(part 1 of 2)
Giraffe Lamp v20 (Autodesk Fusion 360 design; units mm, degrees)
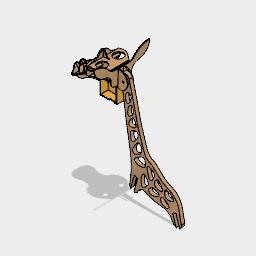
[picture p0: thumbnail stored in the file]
parameter "Thickness" = 3 comment "Material thickness"
parameter "Face1_to_2" = 15 comment "Distance between Face_1 and Face_2"
parameter "M6" = 6 comment "Screw M6"
parameter "Lamp_Socket_Diameter" = 32 comment "Lamp socket"
parameter "Lamp_Wires" = 12 comment "Hole to pass lamp wires"
parameter "Face_2_X" = 165.2206
parameter "pcb_holder_thickness" = 3
parameter "pcb_X" = 52
parameter "pcb_Y" = 49
canvas "Canvas1"
sketch "Body" plane through (0, 0, 0) normal (0, 1, 0) x axis (1, 0, 0)
  curve K1 (162.6914, -108.0349) -> (-15.6199, 232.4021)
  curve K2 (-43.7551, 223.7539) -> (-13.0647, -75.0438)
  curve K3 (-18.2431, 191.7214) -> (-18.2431, 191.7214)
  curve K4 (-7.5042, 158.394) -> (-7.5042, 158.394)
  curve K5 (-2.6903, 124.8814) -> (-2.6903, 124.8814)
  curve K6 (3.0035, 89.8922) -> (3.0035, 89.8922)
  curve K7 (17.7017, 60.8678) -> (17.7017, 60.8678)
  curve K8 (33.8884, 25.1455) -> (33.8884, 25.1455)
  curve K9 (51.6491, 8.676) -> (51.6491, 8.676)
  curve K10 (73.9532, -21.6154) -> (73.9532, -21.6154)
  curve K11 (105.4503, -39.5491) -> (105.4503, -39.5491)
  curve K12 (93.9968, -61.5519) -> (93.9968, -61.5519)
  curve K13 (60.842, -48.4407) -> (60.842, -48.4407)
  curve K14 (34.1675, -21.6154) -> (34.1675, -21.6154)
  curve K15 (15.9684, -79.8842) -> (135.1539, -116.9624)
  curve K16 (11.0078, -92.579) -> (20.9289, -67.1894)
  line L1 (14.1391, -44.6593) -> (2.5936, -41.388)
  line L2 (-10.0602, -86.0485) -> (2.5936, -41.388)
  line L3 (0.817, -91.6784) -> (14.1391, -44.6593)
  line L4 (144.6007, -83.0043) -> (133.1606, -86.627)
  line L5 (145.1038, -124.3424) -> (133.1606, -86.627)
  line L6 (156.8681, -121.7435) -> (144.6007, -83.0043)
  arc A1 centre (1.5341, -76.9705) radius 14.7254 clockwise from (-10.0602, -86.0485) to (-13.0647, -75.0435)
  arc A2 centre (1.5341, -76.9705) radius 14.7254 clockwise from (15.9684, -79.8842) to (0.817, -91.6784)
  arc A3 centre (148.0875, -109.9224) radius 14.7254 clockwise from (145.1038, -124.3424) to (135.1539, -116.9624)
  arc A4 centre (148.0875, -109.9224) radius 14.7254 clockwise from (162.6914, -108.0349) to (156.8681, -121.7435)
  arc A5 centre (-29.8322, 228.5489) radius 14.7254 clockwise from (-43.7487, 223.7354) to (-15.4135, 231.5383)
  circle C1 centre (-30, 220) radius 3
  point P157 (2.5936, -41.388)
  point P158 (14.1391, -44.6593)
  point P161 (133.1606, -86.627)
  point P162 (144.6007, -83.0043)
  dimension "d1" distance P157 P158 = 12
  dimension "d2" distance P161 P162 = 12
  dimension "d773" diameter C1 = 6 (= "M6")
extrude "Extrude1" new body sketch "Body" profile of A5 A4 A2 K1 K15 K2 K3 K4 K5 K6 K7 K8 K9 K10 K11 K12 K13 K14 L1 L2 L3 L4 L5 L6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 along normal blind 12 OffsetX 0 OffsetY 0 OffsetZ 0 AngleZ 0 OffsetX 0 OffsetY 0 OffsetZ 0 AngleZ 0 OffsetX 0 OffsetY 0 OffsetZ 0 AngleZ 0
sketch "Front legs" plane through (24.8016, 0, 7.0271) normal (-0.9621, 0, -0.2726) x axis (-0.2726, 0, 0.9621)
  line L1 (87.9835, 0) -> (39.1135, 0)
  line L2 (87.9835, 12) -> (87.9835, 0)
  line L3 (39.1135, 12) -> (87.9835, 12)
  line L4 (39.1135, 0) -> (39.1135, 12)
  line L5 (256.8278, 66) -> (256.8278, -54)
  line L6 (39.1135, -5.4191) -> (39.1135, 17.4191)
  line L7 (257.1251, -36.0025) -> (256.8278, -54)
  line L8 (87.9835, 0) -> (257.1251, -36.0025)
  line L9 (257.1251, 48.0025) -> (256.8278, 66)
  line L10 (87.9835, 12) -> (257.1251, 48.0025)
  line L11 (87.9835, 12) -> (87.9835, 0)
  line L12 (14.8278, 0) -> (87.9835, 0)
  line L13 (87.9835, 12) -> (14.8278, 12)
  line L14 (39.1135, 12) -> (39.1135, 0)
  line L15 (256.8278, -54) -> (14.8278, 0)
  line L16 (256.8278, 66) -> (14.8278, 12)
  line L17 (39.1135, 6) -> (256.8278, 6)
  line L18 (14.8278, 12) -> (14.8278, 0)
  line L19 (14.8278, 6) -> (39.1135, 6)
  point P6 (256.8278, -54)
  point P8 (257.1251, -36.0025)
  point P7 (256.8278, 66)
  point P10 (257.1251, 48.0025)
  point P9 (87.9835, 0)
  point P11 (87.9835, 12)
  point P17 (256.8278, 6)
  point P21 (14.8278, 6)
  dimension "d22" distance P6 P8 = 18
  dimension "d23" distance P7 P10 = 18
  dimension "d25" distance P9 P11 = 12
  dimension "d26" distance P6 P7 = 120
  dimension "d27" distance P17 P21 = 242
extrude "Extrude1" sketch "Front legs" profile of L1 L2 L3 L4 L5 L6 L8 L10 L11 L12 L13 L14 L15 L16 blind 12
sketch "Rear legs" plane through (107.5328, 0, -34.0521) normal (-0.9533, 0, 0.3019) x axis (0.3019, 0, 0.9533)
  line L1 (163.4204, 0) -> (122.7853, 0)
  line L2 (163.4204, 12) -> (163.4204, 0)
  line L3 (122.7853, 12) -> (163.4204, 12)
  line L4 (122.7853, 0) -> (122.7853, 12)
  line L5 (299.7658, 66) -> (101.7658, 66)
  line L6 (299.7658, -54) -> (299.7658, 66)
  line L7 (101.7658, -54) -> (299.7658, -54)
  line L8 (101.7658, 66) -> (101.7658, -54)
  line L9 (299.7658, 6) -> (101.7658, 6)
  line L10 (122.7853, 0) -> (122.7853, 6)
  line L11 (163.4204, 0) -> (101.7658, 0)
  line L12 (163.4204, 0) -> (163.4204, 6)
  line L13 (122.7853, 6) -> (122.7853, 0)
  line L14 (299.7658, -54) -> (101.7658, 0)
  line L15 (299.7658, -37.1851) -> (163.4204, 0)
  line L16 (299.7658, 66) -> (101.7658, 12)
  line L17 (299.7658, 49.1851) -> (163.4204, 12)
  line L18 (163.4204, 12) -> (101.7658, 12)
  line L19 (122.7853, 6) -> (122.7853, 12)
  line L20 (163.4204, 12) -> (163.4204, 6)
  point P6 (101.7658, 66)
  point P9 (101.7658, -54)
  point P8 (299.7658, -54)
  point P12 (122.7853, 6)
  point P13 (122.7853, 0)
  dimension "d30" distance P6 P9 = 120
  dimension "d31" distance P8 P9 = 198
  dimension "d32" distance P12 P13 = 6
extrude "Extrude1" new body sketch "Rear legs" profile of L1 L2 L3 L4 L6 L10 L11 L12 L13 L14 L15 L16 L17 L18 L19 L20 along normal blind 12
work_plane "WorkPlane1" AlongDistance 250
split "Split1"
remove_body "RemoveBody1"
remove_body "RemoveBody2"
remove_body "RemoveBody1"
remove_body "RemoveBody2"
as_built_joint "As-built1"
as_built_joint "As-built2"
sketch "Face_1" plane through (-225, 0, 0) normal (0, 1, 0) x axis (1, 0, 0)
  line L1 (-103.7104, 33.9723) -> (-78.2357, 50.7747)
  line L2 (-76.5839, 48.2704) -> (-102.5614, 31.1364)
  line L3 (-138.7738, 52.2663) -> (-135.7747, 52.34)
  line L4 (-138.5282, 42.2693) -> (-138.7738, 52.2663)
  line L5 (-179.6538, 49.3613) -> (-176.6874, 48.9131)
  line L6 (-68.885, 40.3968) -> (-28.0159, 61.0056)
  line L7 (-110.8466, 47.166) -> (-103.7104, 33.9723)
  line L8 (-179.6538, 49.3613) -> (-176.6874, 48.9131)
  line L9 (-181.365, 38.0363) -> (-179.6538, 49.3613)
  line L10 (-166.5197, 41.5814) -> (-156.5227, 41.8271)
  line L11 (-138.5282, 42.2693) -> (-138.7738, 52.2663)
  line L12 (-76.5839, 48.2704) -> (-102.5614, 31.1364)
  line L13 (-156.7684, 51.8241) -> (-153.7693, 51.8978)
  line L14 (-156.7684, 51.8241) -> (-153.7693, 51.8978)
  line L15 (-153.5236, 41.9008) -> (-138.5282, 42.2693)
  line L16 (-121.518, 60.6927) -> (-199.0216, 58.7881)
  line L17 (-166.5197, 41.5814) -> (-156.5227, 41.8271)
  line L18 (-121.5917, 63.6918) -> (-121.518, 60.6927)
  line L19 (-135.7747, 52.34) -> (-135.5291, 42.3447)
  line L20 (-181.365, 38.0363) -> (-179.6538, 49.3613)
  line L21 (-121.5917, 63.6918) -> (-121.518, 60.6927)
  line L22 (-110.8466, 47.166) -> (-103.7104, 33.9723)
  line L23 (-68.885, 40.3968) -> (-28.0159, 61.0056)
  line L24 (-176.6874, 48.9131) -> (-178.479, 37.0562)
  line L25 (-176.6874, 48.9131) -> (-178.479, 37.0562)
  line L26 (-78.2357, 50.7747) -> (-76.5839, 48.2704)
  line L27 (-78.2357, 50.7747) -> (-76.5839, 48.2704)
  line L28 (-106.2966, 32.4478) -> (-113.4853, 45.7388)
  line L29 (-153.7693, 51.8978) -> (-153.5236, 41.9008)
  line L30 (-138.7738, 52.2663) -> (-135.7747, 52.34)
  line L31 (-135.7747, 52.34) -> (-135.5291, 42.3447)
  line L32 (-106.2966, 32.4478) -> (-113.4853, 45.7388)
  line L33 (-113.4853, 45.7388) -> (-110.8466, 47.166)
  line L34 (-36.7376, 81.1397) -> (-25.2825, 62.2843)
  line L35 (-135.5291, 42.3447) -> (-127.5161, 42.5416)
  line L36 (-156.5227, 41.8271) -> (-156.7684, 51.8241)
  line L37 (-113.4853, 45.7388) -> (-110.8466, 47.166)
  line L38 (-121.518, 60.6927) -> (-199.0216, 58.7881)
  line L39 (-153.7693, 51.8978) -> (-153.5236, 41.9008)
  line L40 (-39.3015, 79.5821) -> (-36.7376, 81.1397)
  line L41 (-28.0159, 61.0056) -> (-39.3015, 79.5821)
  line L42 (-103.7104, 33.9723) -> (-78.2357, 50.7747)
  line L43 (-135.5291, 42.3447) -> (-127.5161, 42.5416)
  line L44 (-156.5227, 41.8271) -> (-156.7684, 51.8241)
  line L45 (-28.0159, 61.0056) -> (-39.3015, 79.5821)
  line L46 (-36.7376, 81.1397) -> (-25.2825, 62.2843)
  line L47 (-153.5236, 41.9008) -> (-138.5282, 42.2693)
  line L48 (-198.9101, 61.7918) -> (-121.5917, 63.6918)
  line L49 (-39.3015, 79.5821) -> (-36.7376, 81.1397)
  line L50 (-198.9101, 61.7918) -> (-121.5917, 63.6918)
  line L51 (-57.521, 46.1272) -> (-28.0159, 61.0056)
  line L52 (-87.645, 105.8658) -> (-57.521, 46.1272)
  line L53 (-31.0003, 65.918) -> (-198.9101, 61.7918)
  arc A1 centre (-63.0365, 19.3769) radius 21.8183 clockwise from (-76.4762, 36.5645) to (-68.885, 40.3968)
  arc A2 centre (-63.0365, 19.3769) radius 21.8183 clockwise from (-76.4762, 36.5645) to (-68.885, 40.3968)
  arc A3 centre (-95.0013, 60.1969) radius 30.0278 between (-102.5614, 31.1364) and (-76.4762, 36.5645)
  arc A4 centre (-40.0004, 104.4994) radius 15.4992 between (-40, 119.9986) and (-53.1678, 112.6753)
  arc A5 centre (-176.093, 48.8166) radius 12.0003 between (-186.4762, 42.8002) and (-181.365, 38.0363)
  arc A6 centre (-176.0931, 48.8167) radius 12 between (-178.479, 37.0562) and (-166.5197, 41.5814)
  arc A7 centre (-127.0728, 24.5455) radius 18.0016 clockwise from (-127.5161, 42.5416) to (-115.0285, 37.9243)
  circle C1 centre (-26.8048, 98.0857) radius 3
  arc A8 centre (-94.9606, 60.2216) radius 29.9982 between (-115.0285, 37.9243) and (-106.2966, 32.4478)
  arc A9 centre (-178.7415, 61.7856) radius 20.5005 between (-199.0216, 58.7881) and (-186.4762, 42.8002)
  arc A10 centre (-67.6106, 121.6427) radius 17.0002 clockwise from (-53.1678, 112.6753) to (-72.6595, 105.4096)
  arc A11 centre (-80.9733, 78.6726) radius 27.9997 between (-72.6595, 105.4096) and (-99.1949, 99.932)
  arc A12 centre (-95.0013, 60.1969) radius 30.0278 between (-102.5614, 31.1364) and (-76.4762, 36.5645)
  arc A13 centre (-40.0043, 90.0088) radius 29.9898 between (-23.2866, 65.1109) and (-40, 119.9986)
  arc A14 centre (-127.0728, 24.5455) radius 18.0016 clockwise from (-127.5161, 42.5416) to (-115.0285, 37.9243)
  arc A15 centre (-157.7624, 168.2688) radius 90.0004 clockwise from (-99.1949, 99.932) to (-171.2531, 79.2852)
  arc A16 centre (-176.0931, 48.8167) radius 12 between (-178.479, 37.0562) and (-166.5197, 41.5814)
  arc A17 centre (-176.093, 48.8166) radius 12.0003 between (-186.4762, 42.8002) and (-181.365, 38.0363)
  arc A18 centre (-12.9246, 55.6761) radius 14.0138 clockwise from (-25.2825, 62.2843) to (-23.2866, 65.1109)
  arc A19 centre (-178.7415, 61.7856) radius 20.5005 between (-199.0216, 58.7881) and (-186.4762, 42.8002)
  arc A20 centre (-94.9606, 60.2216) radius 29.9982 between (-115.0285, 37.9243) and (-106.2966, 32.4478)
  arc A21 centre (-40.0004, 104.4994) radius 15.4992 between (-40, 119.9986) and (-53.1678, 112.6753)
  arc A22 centre (-174.9843, 54.5747) radius 24.9906 between (-171.2531, 79.2852) and (-198.9101, 61.7918)
  arc A23 centre (-12.9246, 55.6761) radius 14.0138 clockwise from (-25.2825, 62.2843) to (-23.2866, 65.1109)
  arc A24 centre (-67.6106, 121.6427) radius 17.0002 clockwise from (-53.1678, 112.6753) to (-72.6595, 105.4096)
  arc A25 centre (-80.9733, 78.6726) radius 27.9997 between (-72.6595, 105.4096) and (-99.1949, 99.932)
  arc A26 centre (-40.0043, 90.0088) radius 29.9898 between (-23.2866, 65.1109) and (-40, 119.9986)
  circle C2 centre (-26.8048, 98.0857) radius 3
  arc A27 centre (-157.7624, 168.2688) radius 90.0004 clockwise from (-99.1949, 99.932) to (-171.2531, 79.2852)
  arc A28 centre (-174.9847, 54.5754) radius 24.9899 between (-171.2531, 79.2852) and (-198.9101, 61.7918)
  circle C3 centre (-72.583, 75.9965) radius 6
  point P19 (-28.0159, 61.0056)
  point P71 (-57.521, 46.1272)
  point P7 (-103.7104, 33.9723)
  point P20 (-110.8466, 47.166)
  dimension "d42" distance L38 L48 = 3 (= "Thickness")
  dimension "d43" distance L9 L25 = 3 (= "Thickness")
  dimension "d44" distance L39 L44 = 3 (= "Thickness")
  dimension "d45" distance L4 L19 = 3 (= "Thickness")
  dimension "d46" distance L22 L32 = 3 (= "Thickness")
  dimension "d47" distance L1 L2 = 3 (= "Thickness")
  dimension "d48" distance L34 L45 = 3 (= "Thickness")
  dimension "d422" diameter C2 = 6 (= "M6")
  dimension "d720" distance P19 P71 = 33.0441 (= "Face_2_X / 5")
  dimension "d741" diameter C3 = 12 (= "Lamp_Wires")
  dimension "d835" distance P7 P20 = 15 (= "Face1_to_2")
sketch "3e_corne_2" plane through (-200, 0, 0) normal (0, 1, 0) x axis (1, 0, 0)
  line L1 (40.5, 96.1735) -> (10, 96.1735)
  line L2 (40.5, 99.1735) -> (40.5, 96.1735)
  line L3 (10, 101.0735) -> (10, 99.1735)
  line L4 (55.1493, 76.5991) -> (62, 96.1735)
  line L5 (62, 120) -> (10, 101.0735)
  line L6 (10, 99.1735) -> (40.5, 99.1735)
  line L7 (10, 99.1735) -> (40.5, 99.1735)
  line L8 (10, 96.1735) -> (10, 87.0735)
  line L9 (40.5, 96.1735) -> (10, 96.1735)
  line L10 (62, 96.1735) -> (62, 120)
  line L11 (10, 96.1735) -> (10, 87.0735)
  line L12 (10, 101.0735) -> (10, 99.1735)
  line L13 (55.1493, 76.5991) -> (62, 96.1735)
  line L14 (62, 96.1735) -> (62, 120)
  line L15 (62, 120) -> (10, 101.0735)
  line L16 (40.5, 99.1735) -> (40.5, 96.1735)
  arc A1 centre (43.133, 80.8046) radius 12.731 between (31.6545, 75.2979) and (55.1493, 76.5991)
  arc A2 centre (6.685, 55.1792) radius 32.0662 clockwise from (10, 87.0735) to (31.6545, 75.2979)
  arc A3 centre (43.133, 80.8046) radius 12.731 between (31.6545, 75.2979) and (55.1493, 76.5991)
  arc A4 centre (6.685, 55.1792) radius 32.0662 clockwise from (10, 87.0735) to (31.6545, 75.2979)
  dimension "d49" distance L1 L7 = 3 (= "Thickness")
sketch "Face_2" plane through (-375, 0, 175) normal (0, 1, 0) x axis (1, 0, 0)
  line L1 (-19, 32.297) -> (-19, 119.4441)
  line L2 (-1, 119.4441) -> (2, 119.4441)
  line L3 (2, 119.4441) -> (2, 32.297)
  line L4 (-16, 32.297) -> (-1, 32.297)
  line L5 (-16, 119.4441) -> (-16, 32.297)
  line L6 (-19, 119.4441) -> (-16, 119.4441)
  line L7 (-39.3235, 32.297) -> (-19, 32.297)
  line L8 (-54.2349, 53.4678) -> (-39.3235, 32.297)
  line L9 (22.3235, 32.297) -> (38.5, 52.5177)
  line L10 (-1, 32.297) -> (-1, 119.4441)
  line L11 (4, 197.5177) -> (-19, 197.5177)
  line L12 (2, 32.297) -> (22.3235, 32.297)
  arc A1 centre (-7.5, 171.6263) radius 32.1011 between (22.0518, 159.0895) and (24.0559, 177.5177)
  arc A2 centre (-7.5, 171.6263) radius 32.1011 between (-39.0559, 177.5177) and (-37.0518, 159.0895)
  arc A3 centre (-0.5195, 172.9296) radius 25 between (24.0559, 177.5177) and (4, 197.5177)
  arc A4 centre (-83.0811, 139.5624) radius 50 clockwise from (-37.0518, 159.0895) to (-49.5, 102.5177)
  arc A5 centre (68.0811, 139.5624) radius 50 clockwise from (34.5, 102.5177) to (22.0518, 159.0895)
  arc A6 centre (-14.4805, 172.9296) radius 25 between (-19, 197.5177) and (-39.0559, 177.5177)
  arc A7 centre (-24.9091, 75.3904) radius 36.6142 between (-49.5, 102.5177) and (-54.2349, 53.4678)
  arc A8 centre (9.9091, 75.3904) radius 36.6142 between (38.5, 52.5177) and (34.5, 102.5177)
  point P21 (-1, 32.297)
  point P22 (-16, 32.297)
  dimension "d50" distance L1 L5 = 3 (= "Thickness")
  dimension "d51" distance L3 L10 = 3 (= "Thickness")
  dimension "d306" distance P21 P22 = 15 (= "Face1_to_2")
  dimension "d716" distance L4 L11 = 165.2206 (= "Face_2_X")
sketch "Front" plane through (-167.3464, 0, 104.4808) normal (0, 1, 0) x axis (1, 0, 0)
  line L1 (-154.5591, 86) -> (-133.7744, 86)
  line L2 (-103.7, 89) -> (-106.7, 89)
  line L3 (-103.7, 67.9897) -> (-103.7, 89)
  line L4 (-87.0003, 67.9897) -> (-103.7, 67.9897)
  line L5 (-112.7, 120) -> (-97.7, 120)
  line L6 (-133.7744, 86) -> (-133.7744, 89)
  line L7 (-112.7, 98.5) -> (-112.7, 120)
  line L8 (-55.1377, 89) -> (-76.6256, 89)
  line L9 (-106.7, 89) -> (-106.7, 67.9972)
  line L10 (-116.7, 98.5) -> (-112.7, 98.5)
  line L11 (-97.7, 98.5) -> (-93.7, 98.5)
  line L12 (-76.6256, 89) -> (-76.6256, 86)
  line L13 (-76.6256, 86) -> (-55.4786, 86)
  line L14 (-97.7, 120) -> (-97.7, 98.5)
  line L15 (-152.7788, 98.5) -> (-116.7, 98.5)
  line L16 (-106.7, 67.9972) -> (-123, 67.9972)
  line L17 (-133.7744, 89) -> (-154.8709, 89)
  line L18 (-93.7, 98.5) -> (-57.2212, 98.5)
  line L19 (-154.8709, 89) -> (-154.8709, 89.5)
  line L20 (-103.7, 67.9897) -> (-106.7, 67.9972)
  arc A1 centre (-123.0006, 133.0021) radius 65.005 clockwise from (-123, 67.9972) to (-140.162, 70.3034)
  arc A2 centre (-134.8981, 89.5824) radius 19.9847 clockwise from (-140.162, 70.3034) to (-154.5591, 86)
  arc A3 centre (-134.8744, 89.5949) radius 19.9968 clockwise from (-154.8709, 89.5) to (-152.7788, 98.5)
  arc A4 centre (-87.0094, 132.9946) radius 65.005 clockwise from (-69.8455, 70.2966) to (-87.0003, 67.9897)
  arc A5 centre (-75.1425, 89.5666) radius 19.9847 clockwise from (-55.4786, 86) to (-69.8455, 70.2966)
  arc A6 centre (-75.1256, 89.5949) radius 19.9968 clockwise from (-57.2212, 98.5) to (-55.1377, 89)
  point P8 (-97.7, 120)
  point P9 (-112.7, 120)
  point P4 (-106.7, 89)
  point P5 (-103.7, 89)
  dimension "d52" distance L1 L17 = 3 (= "Thickness")
  dimension "d53" distance L8 L13 = 3 (= "Thickness")
  dimension "d323" distance P8 P9 = 15 (= "Face1_to_2")
  dimension "d324" distance P4 P5 = 3 (= "Thickness")
  dimension "d726" distance L3 L14 = 6 (= "( Face1_to_2 - Thickness ) / 2")
sketch "Lamp" plane through (-170.8881, 0, 46.9278) normal (0, 1, 0) x axis (1, 0, 0)
  line L1 (6.5, 71.1848) -> (6.5, 89.0299)
  line L2 (9.5, 71.1848) -> (6.5, 71.1848)
  line L3 (9.5, 71.1848) -> (6.5, 71.1848)
  line L4 (-38.5973, 52.8087) -> (-22.9517, 33.2517)
  line L5 (-38.5973, 52.8087) -> (-22.9517, 33.2517)
  line L6 (-22.9517, 33.2517) -> (37.9374, 33.2517)
  line L7 (37.9374, 33.2517) -> (53.583, 52.8087)
  line L8 (6.5, 71.1848) -> (6.5, 89.0299)
  line L9 (-22.9517, 33.2517) -> (37.9374, 33.2517)
  line L10 (9.5, 89.0299) -> (9.5, 71.1848)
  line L11 (58.8689, 89.0299) -> (9.5, 89.0299)
  line L12 (37.9374, 33.2517) -> (53.583, 52.8087)
  line L13 (6.5, 89.0299) -> (-43.8716, 89.0299)
  line L14 (9.5, 89.0299) -> (9.5, 71.1848)
  line L15 (58.8689, 89.0299) -> (9.5, 89.0299)
  line L16 (6.5, 89.0299) -> (-43.8716, 89.0299)
  arc A1 centre (-9.9035, 75.4816) radius 36.5703 between (-43.8716, 89.0299) and (-38.5973, 52.8087)
  circle C1 centre (-20, 66.2959) radius 16
  arc A2 centre (-9.9147, 75.48) radius 36.5605 between (-43.8716, 89.0299) and (-38.5973, 52.8087)
  circle C2 centre (35, 66.2959) radius 16
  arc A3 centre (24.9027, 75.4904) radius 36.5653 between (53.583, 52.8087) and (58.8689, 89.0299)
  circle C3 centre (35, 66.2959) radius 16
  circle C4 centre (-20, 66.2959) radius 16
  arc A4 centre (24.9081, 75.4896) radius 36.5605 between (53.583, 52.8087) and (58.8689, 89.0299)
  point P5 (-20, 66.2959)
  point P10 (-22.9517, 33.2517)
  dimension "d55" distance L1 L10 = 3 (= "Thickness")
  dimension "d718" distance P5 P10 = 33.0441 (= "Face_2_X / 5")
  dimension "d719" diameter C1 = 32
sketch "Museau_1" plane through (-269.1709, 0, 160.2629) normal (0, 1, 0) x axis (1, 0, 0)
  line L1 (115.5, 120) -> (115.5, 112)
  line L2 (94.5, 120) -> (77, 120)
  line L3 (97.5, 120) -> (97.5, 112)
  line L4 (133, 120) -> (115.5, 120)
  line L5 (94.5, 112) -> (94.5, 120)
  line L6 (115.5, 120) -> (115.5, 112)
  line L7 (115.5, 112) -> (112.5, 112)
  line L8 (97.5, 112) -> (94.5, 112)
  line L9 (112.5, 112) -> (112.5, 120)
  line L10 (115.5, 112) -> (112.5, 112)
  line L11 (112.5, 120) -> (97.5, 120)
  line L12 (93, 102) -> (117, 102)
  line L13 (94.5, 112) -> (94.5, 120)
  line L14 (133, 120) -> (115.5, 120)
  line L15 (112.5, 112) -> (112.5, 120)
  line L16 (112.5, 120) -> (97.5, 120)
  line L17 (94.5, 120) -> (77, 120)
  line L18 (93, 102) -> (117, 102)
  line L19 (97.5, 112) -> (94.5, 112)
  line L20 (97.5, 120) -> (97.5, 112)
  arc A1 centre (93, 118.1111) radius 16.1111 between (77, 120) and (93, 102)
  arc A2 centre (117, 118.1111) radius 16.1111 between (117, 102) and (133, 120)
  arc A3 centre (93, 118.1111) radius 16.1111 between (77, 120) and (93, 102)
  arc A4 centre (117, 118.1111) radius 16.1111 between (117, 102) and (133, 120)
  point P9 (97.5, 120)
  point P13 (112.5, 120)
  dimension "d56" distance L5 L20 = 3 (= "Thickness")
  dimension "d57" distance L1 L9 = 3 (= "Thickness")
  dimension "d309" distance P9 P13 = 15 (= "Face1_to_2")
sketch "Museau_2" plane through (-60.2093, 0, 189.4821) normal (0, 1, 0) x axis (1, 0, 0)
  line L1 (-94.5, 120) -> (-94.5, 110)
  line L2 (-94.5, 110) -> (-97.5, 110)
  line L3 (-112.5, 120) -> (-112.5, 110)
  line L4 (-115.5, 110) -> (-115.5, 120)
  line L5 (-117, 102) -> (-93, 102)
  line L6 (-112.5, 110) -> (-115.5, 110)
  line L7 (-115.5, 120) -> (-131, 120)
  line L8 (-97.5, 120) -> (-112.5, 120)
  line L9 (-79, 120) -> (-94.5, 120)
  line L10 (-117, 102) -> (-93, 102)
  line L11 (-115.5, 110) -> (-115.5, 120)
  line L12 (-112.5, 120) -> (-112.5, 110)
  line L13 (-97.5, 110) -> (-97.5, 120)
  line L14 (-94.5, 110) -> (-97.5, 110)
  line L15 (-94.5, 120) -> (-94.5, 110)
  line L16 (-112.5, 110) -> (-115.5, 110)
  line L17 (-97.5, 110) -> (-97.5, 120)
  line L18 (-97.5, 120) -> (-112.5, 120)
  line L19 (-115.5, 120) -> (-131, 120)
  line L20 (-79, 120) -> (-94.5, 120)
  arc A1 centre (-93, 116.4444) radius 14.4444 between (-93, 102) and (-79, 120)
  arc A2 centre (-117, 116.4444) radius 14.4444 between (-131, 120) and (-117, 102)
  arc A3 centre (-117, 116.4444) radius 14.4444 between (-131, 120) and (-117, 102)
  arc A4 centre (-93, 116.4444) radius 14.4444 between (-93, 102) and (-79, 120)
  point P6 (-112.5, 120)
  point P16 (-97.5, 120)
  dimension "d58" distance L11 L12 = 3 (= "Thickness")
  dimension "d59" distance L1 L17 = 3 (= "Thickness")
  dimension "d310" distance P6 P16 = 15 (= "Face1_to_2")
sketch "Nez" plane through (-269.1709, 0, 223.1285) normal (0, 1, 0) x axis (1, 0, 0)
  line L1 (114.5, 110) -> (111.5, 110)
  line L2 (111.5, 110) -> (111.5, 120)
  line L3 (111.5, 120) -> (96.5, 120)
  line L4 (96.5, 110) -> (93.5, 110)
  line L5 (93.5, 120) -> (73, 120)
  line L6 (114.5, 120) -> (114.5, 110)
  line L7 (137, 120) -> (114.5, 120)
  line L8 (114.5, 120) -> (114.5, 110)
  line L9 (93.5, 110) -> (93.5, 120)
  line L10 (137, 120) -> (114.5, 120)
  line L11 (111.5, 120) -> (96.5, 120)
  line L12 (111.5, 110) -> (111.5, 120)
  line L13 (96.5, 120) -> (96.5, 110)
  line L14 (93.5, 110) -> (93.5, 120)
  line L15 (93.5, 120) -> (73, 120)
  line L16 (114.5, 110) -> (111.5, 110)
  line L17 (96.5, 110) -> (93.5, 110)
  line L18 (96.5, 120) -> (96.5, 110)
  arc A1 centre (126.9178, 120) radius 10.0822 between (129.7089, 110.3119) and (137, 120)
  arc A2 centre (114.5, 107.0208) radius 9.0208 between (114.5, 98) and (123, 104)
  arc A3 centre (95.5, 107.0208) radius 9.0208 between (87, 104) and (95.5, 98)
  arc A4 centre (95.5, 102.5208) radius 4.5208 between (95.5, 98) and (99.5822, 100.5782)
  arc A5 centre (105, 98) radius 6 clockwise from (99.5822, 100.5782) to (110.4178, 100.5782)
  arc A6 centre (83.0822, 120) radius 10.0822 between (73, 120) and (80.2911, 110.3119)
  arc A7 centre (132.5001, 100.6238) radius 10.0822 clockwise from (123, 104) to (129.7089, 110.3119)
  arc A8 centre (114.5, 107.0208) radius 9.0208 between (114.5, 98) and (123, 104)
  arc A9 centre (114.5, 102.5208) radius 4.5208 between (110.4178, 100.5782) and (114.5, 98)
  arc A10 centre (95.5, 102.5208) radius 4.5208 between (95.5, 98) and (99.5822, 100.5782)
  arc A11 centre (77.4999, 100.6238) radius 10.0822 clockwise from (80.2911, 110.3119) to (87, 104)
  arc A12 centre (83.0822, 120) radius 10.0822 between (73, 120) and (80.2911, 110.3119)
  arc A13 centre (77.4999, 100.6238) radius 10.0822 clockwise from (80.2911, 110.3119) to (87, 104)
  arc A14 centre (95.5, 107.0208) radius 9.0208 between (87, 104) and (95.5, 98)
  arc A15 centre (105, 98) radius 6 clockwise from (99.5822, 100.5782) to (110.4178, 100.5782)
  arc A16 centre (126.9178, 120) radius 10.0822 between (129.7089, 110.3119) and (137, 120)
  arc A17 centre (132.5001, 100.6238) radius 10.0822 clockwise from (123, 104) to (129.7089, 110.3119)
  arc A18 centre (114.5, 102.5208) radius 4.5208 between (110.4178, 100.5782) and (114.5, 98)
  point P7 (111.5, 120)
  point P11 (96.5, 120)
  point P23 (93.5, 110)
  point P24 (96.5, 110)
  point P2 (111.5, 110)
  point P3 (114.5, 110)
  dimension "d314" distance P7 P11 = 15 (= "Face1_to_2")
  dimension "d315" distance P23 P24 = 3 (= "Thickness")
  dimension "d316" distance P2 P3 = 3 (= "Thickness")
sketch "Oreilles" plane through (-261.5562, 0, 282.6294) normal (0, 1, 0) x axis (1, 0, 0)
  line L1 (-145, 70) -> (-95, 70)
  line L2 (-85, 100) -> (-85, 105)
  line L3 (-155, 105) -> (-155, 100)
  line L4 (-131.4115, 119.941) -> (-140, 120)
  line L5 (-214.8077, 37.0731) -> (-215, 35)
  line L6 (-110.6026, 92.0007) -> (-113.6025, 92.0213)
  line L7 (-131.4115, 119.941) -> (-140, 120)
  line L8 (-100, 120) -> (-110.4097, 120.0715)
  line L9 (-25, 35) -> (-25.1923, 37.0731)
  line L10 (-113.6025, 92.0213) -> (-113.4087, 120.2294)
  line L11 (-110.4097, 120.0715) -> (-110.6026, 92.0007)
  line L12 (-155, 105) -> (-155, 100)
  line L13 (-113.4087, 120.2294) -> (-128.4087, 120.3325)
  line L14 (-145, 70) -> (-95, 70)
  line L15 (-128.6025, 92.1244) -> (-131.6025, 92.145)
  line L16 (-113.6025, 92.0213) -> (-113.4087, 120.2294)
  line L17 (-128.4087, 120.3325) -> (-128.6025, 92.1244)
  line L18 (-131.6025, 92.145) -> (-131.4115, 119.941)
  line L19 (-128.6025, 92.1244) -> (-131.6025, 92.145)
  line L20 (-113.4087, 120.2294) -> (-128.4087, 120.3325)
  line L21 (-100, 120) -> (-110.4097, 120.0715)
  line L22 (-85, 100) -> (-85, 105)
  line L23 (-110.6026, 92.0007) -> (-113.6025, 92.0213)
  line L24 (-214.8077, 37.0731) -> (-215, 35)
  line L25 (-128.4087, 120.3325) -> (-128.6025, 92.1244)
  line L26 (-110.4097, 120.0715) -> (-110.6026, 92.0007)
  line L27 (-25, 35) -> (-25.1923, 37.0731)
  arc A1 centre (-62.5, 100) radius 22.5 clockwise from (-65, 77.6393) to (-85, 100)
  arc A2 centre (-145, 47.5) radius 22.5 clockwise from (-163, 61) to (-145, 70)
  arc A3 centre (-140, 105) radius 15 between (-140, 120) and (-155, 105)
  arc A4 centre (-177.5, 100) radius 22.5 clockwise from (-155, 100) to (-175, 77.6393)
  arc A5 centre (-140, 105) radius 15 between (-140, 120) and (-155, 105)
  arc A6 centre (-100, 105) radius 15 between (-85, 105) and (-100, 120)
  arc A7 centre (-62.5, 100) radius 22.5 clockwise from (-65, 77.6393) to (-85, 100)
  arc A8 centre (-95, 47.5) radius 22.5 clockwise from (-95, 70) to (-77, 61)
  arc A9 centre (-25, 100) radius 65 between (-77, 61) and (-25, 35)
  arc A10 centre (-70, 32.918) radius 45 between (-25.1923, 37.0731) and (-65, 77.6393)
  arc A11 centre (-215, 100) radius 65 between (-215, 35) and (-163, 61)
  arc A12 centre (-145, 47.5) radius 22.5 clockwise from (-163, 61) to (-145, 70)
  arc A13 centre (-215, 100) radius 65 between (-215, 35) and (-163, 61)
  arc A14 centre (-170, 32.918) radius 45 between (-175, 77.6393) and (-214.8077, 37.0731)
  arc A15 centre (-70, 32.918) radius 45 between (-25.1923, 37.0731) and (-65, 77.6393)
  arc A16 centre (-177.5, 100) radius 22.5 clockwise from (-155, 100) to (-175, 77.6393)
  arc A17 centre (-100, 105) radius 15 between (-85, 105) and (-100, 120)
  arc A18 centre (-170, 32.918) radius 45 between (-175, 77.6393) and (-214.8077, 37.0731)
  arc A19 centre (-25, 100) radius 65 between (-77, 61) and (-25, 35)
  arc A20 centre (-95, 47.5) radius 22.5 clockwise from (-95, 70) to (-77, 61)
  point P29 (-113.4087, 120.2294)
  point P33 (-128.4087, 120.3325)
  point P10 (-131.6025, 92.145)
  point P34 (-128.6025, 92.1244)
  point P18 (-113.6025, 92.0213)
  point P19 (-110.6026, 92.0007)
  dimension "d320" distance P29 P33 = 15 (= "Face1_to_2")
  dimension "d321" distance P10 P34 = 3 (= "Thickness")
  dimension "d322" distance P18 P19 = 3 (= "Thickness")
sketch "Thug Life glasses" plane through (-267.3038, 0, 269.0799) normal (0, 1, 0) x axis (1, 0, 0)
  line L1 (78.8754, 83.8) -> (105.8754, 83.8)
  line L2 (78.8754, 83.8) -> (105.8754, 83.8)
  line L3 (80.3754, 115.7196) -> (76.0938, 115.6746)
  line L4 (32.6754, 93.2196) -> (32.6754, 83.8)
  line L5 (40.1754, 93.2196) -> (32.6754, 93.2196)
  line L6 (40.1754, 100.7196) -> (40.1754, 93.2196)
  line L7 (47.6754, 100.7196) -> (40.1754, 100.7196)
  line L8 (47.6754, 108.2196) -> (47.6754, 100.7196)
  line L9 (55.1754, 108.2196) -> (47.6754, 108.2196)
  line L10 (55.1754, 115.7196) -> (55.1754, 108.2196)
  line L11 (80.3754, 115.7196) -> (55.1754, 115.7196)
  line L12 (80.3754, 108.2196) -> (80.3754, 115.7196)
  line L13 (87.8754, 108.2196) -> (80.3754, 108.2196)
  line L14 (87.8754, 100.7196) -> (87.8754, 108.2196)
  line L15 (95.3754, 100.7196) -> (87.8754, 100.7196)
  line L16 (98.3754, 91.3) -> (98.3754, 98.8)
  line L17 (105.8754, 91.3) -> (98.3754, 91.3)
  line L18 (105.8754, 120) -> (105.8754, 83.8)
  line L19 (32.6754, 83.8) -> (105.8754, 83.8)
  line L20 (95.3754, 98.8) -> (95.3754, 100.7196)
  line L21 (98.3754, 98.8) -> (95.3754, 98.8)
  line L22 (123.8754, 108.2196) -> (131.3754, 108.2196)
  line L23 (116.3754, 98.8) -> (116.3754, 100.7196)
  line L24 (113.3754, 91.3) -> (113.3754, 98.8)
  line L25 (131.3754, 115.7196) -> (156.5754, 115.7196)
  line L26 (131.3754, 108.2196) -> (131.3754, 115.7196)
  line L27 (105.8754, 91.3) -> (113.3754, 91.3)
  line L28 (123.8754, 100.7196) -> (123.8754, 108.2196)
  line L29 (132.8754, 83.8) -> (105.8754, 83.8)
  line L30 (179.0754, 83.8) -> (105.8754, 83.8)
  line L31 (113.3754, 98.8) -> (116.3754, 98.8)
  line L32 (132.8754, 83.8) -> (105.8754, 83.8)
  line L33 (116.3754, 100.7196) -> (123.8754, 100.7196)
  line L34 (171.5754, 93.2196) -> (179.0754, 93.2196)
  line L35 (156.5754, 115.7196) -> (156.5754, 108.2196)
  line L36 (179.0754, 93.2196) -> (179.0754, 83.8)
  line L37 (156.5754, 108.2196) -> (164.0754, 108.2196)
  line L38 (164.0754, 100.7196) -> (171.5754, 100.7196)
  line L39 (171.5754, 100.7196) -> (171.5754, 93.2196)
  line L40 (164.0754, 108.2196) -> (164.0754, 100.7196)
  line L41 (131.3754, 115.7196) -> (135.6571, 115.6746)
  point P11 (55.1754, 115.7196)
  point P12 (80.3754, 115.7196)
  dimension "d805" distance L16 L20 = 3 (= "Thickness")
  dimension "d806" distance L20 L23 = 21 (= "Face1_to_2 + 2 * Thickness")
  dimension "d833" distance P11 P12 = 25.2 (= "d806 * 1.2")
  dimension "d834" distance L1 L21 = 15 (= "Face1_to_2")
canvas "Canvas2" sketch "Thug Life glasses"
sketch "Yeux_&_3e_corne" plane through (-140.3123, 0, 141.2004) normal (0, 1, 0) x axis (1, 0, 0)
  line L1 (-4, -81.6513) -> (-21.1, -81.6513)
  line L2 (-4, -72.5513) -> (-4, -81.6513)
  line L3 (5.5, -47.2323) -> (5.5, -72.5513)
  line L4 (-4, -84.6513) -> (-4, -103.5513)
  line L5 (5.5, -72.5513) -> (-4, -72.5513)
  line L6 (-4, -103.5513) -> (-41.5, -103.5513)
  line L7 (-21.1, -81.6513) -> (-21.1, -84.6513)
  line L8 (-4, -81.6513) -> (-21.1, -81.6513)
  line L9 (-4, -103.5513) -> (-41.5, -103.5513)
  line L10 (5.5, -72.5513) -> (-4, -72.5513)
  line L11 (-21.1, -84.6513) -> (-4, -84.6513)
  line L12 (-21.1, -81.6513) -> (-21.1, -84.6513)
  line L13 (5.5, -47.2323) -> (5.5, -72.5513)
  line L14 (-4, -72.5513) -> (-4, -81.6513)
  line L15 (-4, -84.6513) -> (-4, -103.5513)
  line L16 (-21.1, -84.6513) -> (-4, -84.6513)
  arc A1 centre (7.5, -69.5513) radius 22.4084 clockwise from (-12.4352, -59.3179) to (5.5, -47.2323)
  closed curve K1 centre (-31.2141, -88.1534)
  arc A2 centre (7.5, -69.5513) radius 22.4084 clockwise from (-12.4352, -59.3179) to (5.5, -47.2323)
  closed curve K2 centre (-31.2141, -88.1534)
  arc A3 centre (-43.5335, -25.6181) radius 45.8561 clockwise from (-12.4352, -59.3179) to (-38.7062, -71.2193)
  dimension "d67" distance L8 L16 = 3 (= "Thickness")
extrude "Extrude1" new body sketch "Face_1" profile of A1 A2 L1 L2 L3 L4 A3 L5 A4 L6 L7 L8 L9 A5 A6 A7 C1 L10 L11 A8 L12 L13 L14 A9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 along normal blind 3 (= "Thickness") OffsetX 0 OffsetY 0 OffsetZ 0 AngleZ 0 OffsetX 0 OffsetY 0 OffsetZ 0 AngleZ 0 OffsetX 0 OffsetY 0 OffsetZ 0 AngleZ 0 OffsetX 0 OffsetY 0 OffsetZ 0 AngleZ 0 OffsetX 0 OffsetY 0 OffsetZ 0 AngleZ 0 OffsetX 0 OffsetY 0 OffsetZ 0 AngleZ 0 OffsetX 0 OffsetY 0 OffsetZ 0 AngleZ 0 OffsetX 0 OffsetY 0 OffsetZ 0 AngleZ 0 OffsetX 0 OffsetY 0 OffsetZ 0 AngleZ 0 OffsetX 0 OffsetY 0 OffsetZ 0 AngleZ 0 OffsetX 0 OffsetY 0 OffsetZ 0 AngleZ 0 OffsetX 0 OffsetY 0 OffsetZ 0 AngleZ 0 OffsetX 0 OffsetY 0 OffsetZ 0 AngleZ 0 OffsetX 0 OffsetY 0 OffsetZ 0 AngleZ 0 OffsetX 0 OffsetY 0 OffsetZ 0 AngleZ 0 OffsetX 0 OffsetY 0 OffsetZ 0 AngleZ 0 OffsetX 0 OffsetY 0 OffsetZ 0 AngleZ 0 OffsetX 0 OffsetY 0 OffsetZ 0 AngleZ 0 OffsetX 0 OffsetY 0 OffsetZ 0 AngleZ 0 OffsetX 0 OffsetY 0 OffsetZ 0 AngleZ 0 OffsetX 0 OffsetY 0 OffsetZ 0 AngleZ 0 OffsetX 0 OffsetY 0 OffsetZ 0 AngleZ 0 OffsetX 0 OffsetY 0 OffsetZ 0 AngleZ 0 OffsetX 0 OffsetY 0 OffsetZ 0 AngleZ 0 OffsetX 0 OffsetY 0 OffsetZ 0 AngleZ 0 OffsetX 0 OffsetY 0 OffsetZ 0 AngleZ 0 OffsetX 0 OffsetY 0 OffsetZ 0 AngleZ 0 OffsetX 0 OffsetY 0 OffsetZ 0 AngleZ 0 OffsetX 0 OffsetY 0 OffsetZ 0 AngleZ 0 OffsetX 0 OffsetY 0 OffsetZ 0 AngleZ 0 OffsetX 0 OffsetY 0 OffsetZ 0 AngleZ 0
extrude "Extrude1" new body sketch "3e_corne_2" along normal blind 3 (= "Thickness")
extrude "Extrude1" new body sketch "Face_2" along normal blind 3 (= "Thickness")
extrude "Extrude1" new body sketch "Lamp" along normal blind 3 (= "Thickness")
extrude "Extrude1" new body sketch "Museau_1" along normal blind 3 (= "Thickness") OffsetX 0 OffsetY 0 OffsetZ 0 AngleZ 0 OffsetX 0 OffsetY 0 OffsetZ 0 AngleZ 0 OffsetX 0 OffsetY 0 OffsetZ 0 AngleZ 0 OffsetX 0 OffsetY 0 OffsetZ 0 AngleZ 0
extrude "Extrude1" new body sketch "Museau_2" along normal blind 3 (= "Thickness") OffsetX 0 OffsetY 0 OffsetZ 0 AngleZ 0 OffsetX 0 OffsetY 0 OffsetZ 0 AngleZ 0
extrude "Extrude1" new body sketch "Nez" along normal blind 3 (= "Thickness") OffsetX 0 OffsetY 0 OffsetZ 0 AngleZ 0 OffsetX 0 OffsetY 0 OffsetZ 0 AngleZ 0 OffsetX 0 OffsetY 0 OffsetZ 0 AngleZ 0 OffsetX 0 OffsetY 0 OffsetZ 0 AngleZ 0 OffsetX 0 OffsetY 0 OffsetZ 0 AngleZ 0 OffsetX 0 OffsetY 0 OffsetZ 0 AngleZ 0
extrude "Extrude1" new body sketch "Yeux_&_3e_corne" profile of L1 L2 L3 L4 L5 A1 K1 L6 L7 L8 L9 L10 L11 A2 L12 L13 L14 L15 L16 K2 along normal blind 3 (= "Thickness")
extrude "Extrude1" new body sketch "Oreilles" along normal blind 3 (= "Thickness") OffsetX 0 OffsetY 0 OffsetZ 0 AngleZ 0 OffsetX 0 OffsetY 0 OffsetZ 0 AngleZ 0 OffsetX 0 OffsetY 0 OffsetZ 0 AngleZ 0 OffsetX 0 OffsetY 0 OffsetZ 0 AngleZ 0 OffsetX 0 OffsetY 0 OffsetZ 0 AngleZ 0 OffsetX 0 OffsetY 0 OffsetZ 0 AngleZ 0 OffsetX 0 OffsetY 0 OffsetZ 0 AngleZ 0 OffsetX 0 OffsetY 0 OffsetZ 0 AngleZ 0 OffsetX 0 OffsetY 0 OffsetZ 0 AngleZ 0 OffsetX 0 OffsetY 0 OffsetZ 0 AngleZ 0 OffsetX 0 OffsetY 0 OffsetZ 0 AngleZ 0 OffsetX 0 OffsetY 0 OffsetZ 0 AngleZ 0
copy_paste "CopyPaste1"
copy_paste "CopyPaste2"
extrude "Extrude1" new body sketch "Front" profile of L1 L2 L3 L4 L5 L6 L7 L8 L9 L10 A1 A2 L11 L12 A3 L13 A4 L14 L15 L16 A5 L17 A6 L18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 along normal blind 3 (= "Thickness") OffsetX 0 OffsetY 0 OffsetZ 0 AngleZ 0
joint "Assemble1" alignAngle -90 alignOffsetX 0 alignOffsetY 0 alignOffsetZ 0
joint "Assemble2" alignAngle -90 alignOffsetX 0 alignOffsetY 0 alignOffsetZ 0
joint "Assemble4" alignAngle 90 alignOffsetX 0 alignOffsetY 0 alignOffsetZ 0
joint "Assemble5" alignAngle -90 alignOffsetX 0 alignOffsetY 0 alignOffsetZ 0
joint "Assemble6" alignAngle -90 alignOffsetX 0 alignOffsetY 0 alignOffsetZ 0
joint "Assemble7" alignAngle -90 alignOffsetX 0 alignOffsetY 0 alignOffsetZ 0
joint "Assemble9" alignAngle 90 alignOffsetX 0 alignOffsetY 0 alignOffsetZ 0
joint "Assemble10" alignAngle -90 alignOffsetX 0 alignOffsetY 0 alignOffsetZ 0
joint "Assemble13" alignAngle -90 alignOffsetX 0 alignOffsetY 0 alignOffsetZ 0
joint "Assemble14" alignAngle -90 alignOffsetX 0 alignOffsetY 0 alignOffsetZ 0
joint "Assemble15" alignAngle -90 alignOffsetX 0 alignOffsetY 0 alignOffsetZ 0
joint "Assemble19" alignAngle 90 alignOffsetX 0 alignOffsetY 0 alignOffsetZ 0
copy_paste "CutPaste1"
copy_paste "CutPaste2"
copy_paste "CutPaste3"
copy_paste "CutPaste4"
copy_paste "CutPaste5"
copy_paste "CutPaste6"
copy_paste "CutPaste7"
copy_paste "CutPaste9"
copy_paste "CutPaste10"
copy_paste "CutPaste11"
copy_paste "CutPaste12"
copy_paste "CutPaste13"
sketch "Sketch2" plane through (0, 0, 5.9808) normal (0, 0, -1) x axis (-1, 0, 0)
  line L1 (320.1252, 0) -> (280.0464, 0)
  line L2 (320.1252, 3) -> (320.1252, 0)
  line L3 (280.0464, 3) -> (320.1252, 3)
  line L4 (280.0464, 0) -> (280.0464, 3)
  line L5 (262.0464, 0) -> (265.0464, 0)
  line L6 (262.0464, 3) -> (262.0464, 0)
  line L7 (265.0464, 3) -> (262.0464, 3)
  line L8 (265.0464, 0) -> (265.0464, 3)
  line L9 (283.0464, 0) -> (280.0464, 0)
  line L10 (283.0464, 3) -> (283.0464, 0)
  line L11 (280.0464, 3) -> (283.0464, 3)
  line L12 (280.0464, 0) -> (280.0464, 3)
  point P6 (265.0464, 0)
  point P7 (262.0464, 0)
  point P9 (265.0464, 3)
  point P11 (280.0464, 0)
  point P12 (283.0464, 0)
  point P14 (280.0464, 3)
  dimension "d647" distance P6 P7 = 3 (= "Thickness")
  dimension "d648" distance P6 P9 = 3 (= "Thickness")
  dimension "d649" distance P11 P12 = 3 (= "Thickness")
  dimension "d650" distance P11 P14 = 3 (= "Thickness")
joint "Assemble2" alignAngle 90 alignOffsetX 0 alignOffsetY 0 alignOffsetZ 0
joint "Assemble3" alignAngle 90 alignOffsetX 0 alignOffsetY 0 alignOffsetZ 0
position "Position6"
sketch "Sketch1" plane through (0, 3, 0) normal (0, 1, 0) x axis (-1, 0, 0)
  line L1 (190, -96.1735) -> (159.5, -96.1735)
  line L2 (190, -87.0735) -> (190, -96.1735)
  line L3 (138, -96.1735) -> (144.8507, -76.5991)
  line L4 (138, -120) -> (138, -96.1735)
  line L5 (190, -101.0735) -> (138, -120)
  line L6 (190, -99.1735) -> (190, -101.0735)
  line L7 (159.5, -99.1735) -> (190, -99.1735)
  line L8 (159.5, -96.1735) -> (159.5, -99.1735)
  line L9 (156.5, -61.7546) -> (156.5, -87.0735)
  line L10 (159.5, -61.7546) -> (156.5, -61.7546)
  line L11 (159.5, -87.0735) -> (159.5, -61.7546)
  line L12 (156.5, -87.0735) -> (159.5, -87.0735)
  line L13 (160.0609, -83.2576) -> (177.7875, -81.2041)
  line L14 (177.7875, -81.2041) -> (160.0609, -83.2576)
  line L15 (171.0918, -85.3619) -> (216.5552, -80.0634)
  line L16 (196.3867, -82.0697) -> (160.4061, -86.2377)
  line L17 (177.7875, -81.2041) -> (178.1327, -84.1842)
  line L18 (160.4061, -86.2377) -> (178.1327, -84.1842)
  line L19 (160.0609, -83.2576) -> (160.4061, -86.2377)
  line L20 (177.7875, -81.2041) -> (160.0609, -83.2576)
  line L21 (178.1327, -84.1842) -> (177.7875, -81.2041)
  line L22 (190, -82.8095) -> (190, -96.1735)
  line L23 (178.1327, -84.1842) -> (190, -82.8095)
  line L24 (178.1327, -84.1842) -> (177.7875, -81.2041)
  line L25 (175.033, -81.5232) -> (177.7875, -81.2041)
  line L26 (159.5, -96.1735) -> (190, -96.1735)
  line L27 (159.5, -99.1735) -> (159.5, -96.1735)
  line L28 (190, -99.1735) -> (159.5, -99.1735)
  line L29 (190, -101.0735) -> (190, -99.1735)
  line L30 (138, -120) -> (190, -101.0735)
  line L31 (138, -96.1735) -> (138, -120)
  line L32 (144.8507, -76.5991) -> (138, -96.1735)
  line L33 (190, -96.1735) -> (190, -87.0735)
  line L34 (175.033, -81.5232) -> (177.7875, -81.2041)
  curve K1 (177.7875, -81.2041) -> (144.8507, -76.5991)
  curve K2 (174.4186, -81.0396) -> (164.7484, -70.8064)
  arc A1 centre (193.315, -55.1792) radius 32.0662 clockwise from (190, -87.0735) to (168.3455, -75.2979)
  arc A2 centre (156.867, -80.8046) radius 12.731 clockwise from (144.8507, -76.5991) to (168.3455, -75.2979)
  arc A3 centre (156.867, -80.8046) radius 12.731 clockwise from (144.8507, -76.5991) to (168.3455, -75.2979)
  arc A4 centre (193.315, -55.1792) radius 32.0662 clockwise from (190, -87.0735) to (168.3455, -75.2979)
extrude "Extrude2" add sketch "Sketch1" profile of A1 A2 L9 L10 L11 L13 L14 L15 L16 L17 L20 L21 L22 L23 L24 L25 L34 K1 no distance stored
joint "Assemble4" alignAngle 90 alignOffsetX 0 alignOffsetY 0 alignOffsetZ 0
position "Position7"
sketch "Sketch2" plane through (0, 3, 0) normal (0, 1, 0) x axis (-1, 0, 0)
  line L1 (394, -22.5177) -> (371, -22.5177)
  line L2 (414.3235, 142.703) -> (429.2349, 121.5322)
  line L3 (394, 142.703) -> (414.3235, 142.703)
  line L4 (394, 55.5559) -> (394, 142.703)
  line L5 (391, 55.5559) -> (394, 55.5559)
  line L6 (391, 142.703) -> (391, 55.5559)
  line L7 (376, 142.703) -> (391, 142.703)
  line L8 (376, 55.5559) -> (376, 142.703)
  line L9 (373, 55.5559) -> (376, 55.5559)
  line L10 (373, 142.703) -> (373, 55.5559)
  line L11 (352.6765, 142.703) -> (373, 142.703)
  line L12 (336.5, 122.4823) -> (352.6765, 142.703)
  arc A1 centre (306.9189, 35.4376) radius 50 clockwise from (340.5, 72.4823) to (352.9482, 15.9105)
  arc A2 centre (382.5, 3.3737) radius 32.1011 clockwise from (350.9441, -2.5177) to (352.9482, 15.9105)
  arc A3 centre (375.5195, 2.0704) radius 25 clockwise from (371, -22.5177) to (350.9441, -2.5177)
  arc A4 centre (389.4805, 2.0704) radius 25 clockwise from (414.0559, -2.5177) to (394, -22.5177)
  arc A5 centre (382.5, 3.3737) radius 32.1011 clockwise from (412.0518, 15.9105) to (414.0559, -2.5177)
  arc A6 centre (458.0811, 35.4376) radius 50 clockwise from (412.0518, 15.9105) to (424.5, 72.4823)
  arc A7 centre (399.9091, 99.6096) radius 36.6142 clockwise from (429.2349, 121.5322) to (424.5, 72.4823)
  arc A8 centre (365.0909, 99.6096) radius 36.6142 clockwise from (340.5, 72.4823) to (336.5, 122.4823)
  closed curve K1 centre (356.5, 120.1478)
  closed curve K2 centre (411.5, 120.1478)
  circle C1 centre (411.5, 120.1478) radius 6
  circle C2 centre (356.5, 120.1478) radius 6
  dimension "d736" diameter C1 = 12 (= "Lamp_Wires")
  dimension "d737" diameter C2 = 12 (= "Lamp_Wires")
extrude "Extrude3" sketch "Sketch2" profile of C1 C2 no distance stored
sketch "Sketch1" plane through (0, 3, 0) normal (0, 1, 0) x axis (-1, 0, 0)
  line L1 (394, -22.5177) -> (371, -22.5177)
  line L2 (414.3235, 142.703) -> (429.2349, 121.5322)
  line L3 (394, 142.703) -> (414.3235, 142.703)
  line L4 (394, 55.5559) -> (394, 142.703)
  line L5 (391, 55.5559) -> (394, 55.5559)
  line L6 (391, 142.703) -> (391, 55.5559)
  line L7 (376, 142.703) -> (391, 142.703)
  line L8 (376, 55.5559) -> (376, 142.703)
  line L9 (373, 55.5559) -> (376, 55.5559)
  line L10 (373, 142.703) -> (373, 55.5559)
  line L11 (352.6765, 142.703) -> (373, 142.703)
  line L12 (336.5, 122.4823) -> (352.6765, 142.703)
  arc A1 centre (306.9189, 35.4376) radius 50 clockwise from (340.5, 72.4823) to (352.9482, 15.9105)
  arc A2 centre (382.5, 3.3737) radius 32.1011 clockwise from (350.9441, -2.5177) to (352.9482, 15.9105)
  arc A3 centre (375.5195, 2.0704) radius 25 clockwise from (371, -22.5177) to (350.9441, -2.5177)
  arc A4 centre (389.4805, 2.0704) radius 25 clockwise from (414.0559, -2.5177) to (394, -22.5177)
  arc A5 centre (382.5, 3.3737) radius 32.1011 clockwise from (412.0518, 15.9105) to (414.0559, -2.5177)
  arc A6 centre (458.0811, 35.4376) radius 50 clockwise from (412.0518, 15.9105) to (424.5, 72.4823)
  arc A7 centre (399.9091, 99.6096) radius 36.6142 clockwise from (429.2349, 121.5322) to (424.5, 72.4823)
  arc A8 centre (365.0909, 99.6096) radius 36.6142 clockwise from (340.5, 72.4823) to (336.5, 122.4823)
  circle C1 centre (356.5, 120.1478) radius 6
  circle C2 centre (411.5, 120.1478) radius 6
sketch "Sketch3" plane through (0, 3, 0) normal (0, 1, 0) x axis (-1, 0, 0)
  line L1 (280.0464, 5.9808) -> (280.0464, -15.5192)
  line L2 (320.1252, 5.9808) -> (280.0464, 5.9808)
  line L3 (322.2173, 15.4808) -> (322.2173, 14.9808)
  line L4 (301.1207, 15.4808) -> (322.2173, 15.4808)
  line L5 (301.1207, 18.4808) -> (301.1207, 15.4808)
  line L6 (321.9055, 18.4808) -> (301.1207, 18.4808)
  line L7 (274.0464, 36.4836) -> (290.3464, 36.4836)
  line L8 (274.0464, 15.4808) -> (274.0464, 36.4836)
  line L9 (271.0464, 15.4808) -> (274.0464, 15.4808)
  line L10 (271.0464, 36.4911) -> (271.0464, 15.4808)
  line L11 (254.3467, 36.4911) -> (271.0464, 36.4911)
  line L12 (243.972, 18.4808) -> (222.8249, 18.4808)
  line L13 (243.972, 15.4808) -> (243.972, 18.4808)
  line L14 (222.4841, 15.4808) -> (243.972, 15.4808)
  line L15 (265.0464, 5.9808) -> (224.5675, 5.9808)
  line L16 (265.0464, -15.5192) -> (265.0464, 5.9808)
  line L17 (280.0464, -15.5192) -> (265.0464, -15.5192)
  arc A1 centre (302.2207, 14.8859) radius 19.9968 clockwise from (322.2173, 14.9808) to (320.1252, 5.9808)
  arc A2 centre (302.2445, 14.8984) radius 19.9847 clockwise from (307.5083, 34.1774) to (321.9055, 18.4808)
  arc A3 centre (290.3469, -28.5213) radius 65.005 clockwise from (290.3464, 36.4836) to (307.5083, 34.1774)
  arc A4 centre (254.3558, -28.5138) radius 65.005 clockwise from (237.1918, 34.1842) to (254.3467, 36.4911)
  arc A5 centre (242.4889, 14.9143) radius 19.9847 clockwise from (222.8249, 18.4808) to (237.1918, 34.1842)
  arc A6 centre (242.472, 14.8859) radius 19.9968 clockwise from (224.5675, 5.9808) to (222.4841, 15.4808)
sketch "Sketch1"
  line L1 (147.7556, 85.8702) -> (147.2324, 64.1406)
  line L2 (102.0532, 83.3632) -> (147.7556, 85.8702)
  line L3 (99.3038, 72.6998) -> (68.243, 74.6037)
  line L4 (99.1203, 69.7054) -> (99.3038, 72.6998)
  line L5 (68.6605, 71.5725) -> (99.1203, 69.7054)
  line L6 (69.0512, 56.5776) -> (68.6605, 71.5725)
  line L7 (66.0522, 56.4995) -> (69.0512, 56.5776)
  line L8 (65.6587, 71.6049) -> (66.0522, 56.4995)
  line L9 (45.2506, 48.4532) -> (52.2952, 52.277)
  line L10 (50.0202, 39.6659) -> (45.2506, 48.4532)
  line L11 (47.3835, 38.2348) -> (50.0202, 39.6659)
  line L12 (42.6131, 47.0236) -> (47.3835, 38.2348)
  line L13 (29.4299, 39.868) -> (42.6131, 47.0236)
  line L14 (34.2003, 31.0792) -> (29.4299, 39.868)
  line L15 (31.5637, 29.6481) -> (34.2003, 31.0792)
  line L16 (26.7932, 38.4369) -> (31.5637, 29.6481)
  line L17 (18.0045, 33.6665) -> (26.7932, 38.4369)
  line L18 (12.8448, 22.2422) -> (5.3812, 31.6278)
  line L19 (10.4968, 20.3749) -> (12.8448, 22.2422)
  line L20 (3.368, 29.3395) -> (10.4968, 20.3749)
  line L21 (66.543, 39.5318) -> (-1.594, 2.5482)
  line L22 (67.9741, 36.8951) -> (66.543, 39.5318)
  line L23 (0, 0) -> (67.9741, 36.8951)
  line L24 (150.2315, 64.0684) -> (150.7626, 86.1243)
  line L25 (147.2324, 64.1406) -> (150.2315, 64.0684)
  line L26 (145, 39) -> (93, 39)
  line L27 (145, -10) -> (145, 39)
  line L28 (93, -10) -> (145, -10)
  line L29 (93, 39) -> (93, -10)
  line L30 (148, 42) -> (90, 42)
  line L31 (148, -13) -> (148, 42)
  line L32 (90, -13) -> (148, -13)
  line L33 (90, 42) -> (90, -13)
  circle C1 centre (167.2895, 54.3293) radius 3
  circle C2 centre (116.5934, 50.6584) radius 6
  arc A1 centre (96.645, 104.5006) radius 21.8183 clockwise from (102.0532, 83.3632) to (93.562, 82.9012)
  arc A2 centre (89.2831, 53.1798) radius 30.0278 clockwise from (68.243, 74.6037) to (93.562, 82.9012)
  arc A3 centre (89.3307, 53.1787) radius 29.9982 clockwise from (60.819, 62.5045) to (65.6587, 71.6049)
  arc A4 centre (43.7087, 68.0987) radius 18.0016 clockwise from (60.819, 62.5045) to (52.2952, 52.277)
  arc A5 centre (13.312, 22.6221) radius 12 clockwise from (5.3812, 31.6278) to (18.0045, 33.6665)
  arc A6 centre (13.312, 22.6222) radius 12.0003 clockwise from (1.3118, 22.6619) to (3.368, 29.3395)
  arc A7 centre (17.481, 10.0592) radius 20.5005 clockwise from (-1.594, 2.5482) to (1.3118, 22.6619)
  arc A8 centre (17.1435, 18.1831) radius 24.9906 clockwise from (32.6959, -1.3783) to (0, 0)
  arc A9 centre (88.7482, -71.7929) radius 90.0004 clockwise from (32.6959, -1.3783) to (105.4552, 16.6432)
  arc A10 centre (110.6538, 44.1561) radius 27.9997 clockwise from (131.1891, 25.1222) to (105.4552, 16.6432)
  arc A11 centre (143.6581, 13.5666) radius 17.0002 clockwise from (131.1891, 25.1222) to (151.7083, 28.54)
  arc A12 centre (159.0475, 42.1914) radius 15.4992 clockwise from (166.774, 28.7554) to (151.7083, 28.54)
  arc A13 centre (151.8208, 54.7513) radius 29.9898 clockwise from (153.902, 84.6688) to (166.774, 28.7554)
  arc A14 centre (158.1816, 98.0132) radius 14.0138 clockwise from (153.902, 84.6688) to (150.7626, 86.1243)
  point P57 (93, 39)
  point P60 (93, -10)
  point P59 (145, -10)
  dimension "d742" distance P57 P60 = 49 (= "pcb_Y")
  dimension "d743" distance P59 P60 = 52 (= "pcb_X")
  dimension "d744" = 3 (= "pcb_holder_thickness")
extrude "Extrude1" new body sketch "Sketch1" profile of A9 A10 A11 L26 L27 L28 L29 L30 L31 L32 L33 blind 3 (= "pcb_holder_thickness")
extrude "Extrude2" add sketch "Sketch1" profile of A9 A11 L26 L27 L28 L29 L30 L31 L32 L33 blind 28 (= "25 mm + pcb_holder_thickness")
